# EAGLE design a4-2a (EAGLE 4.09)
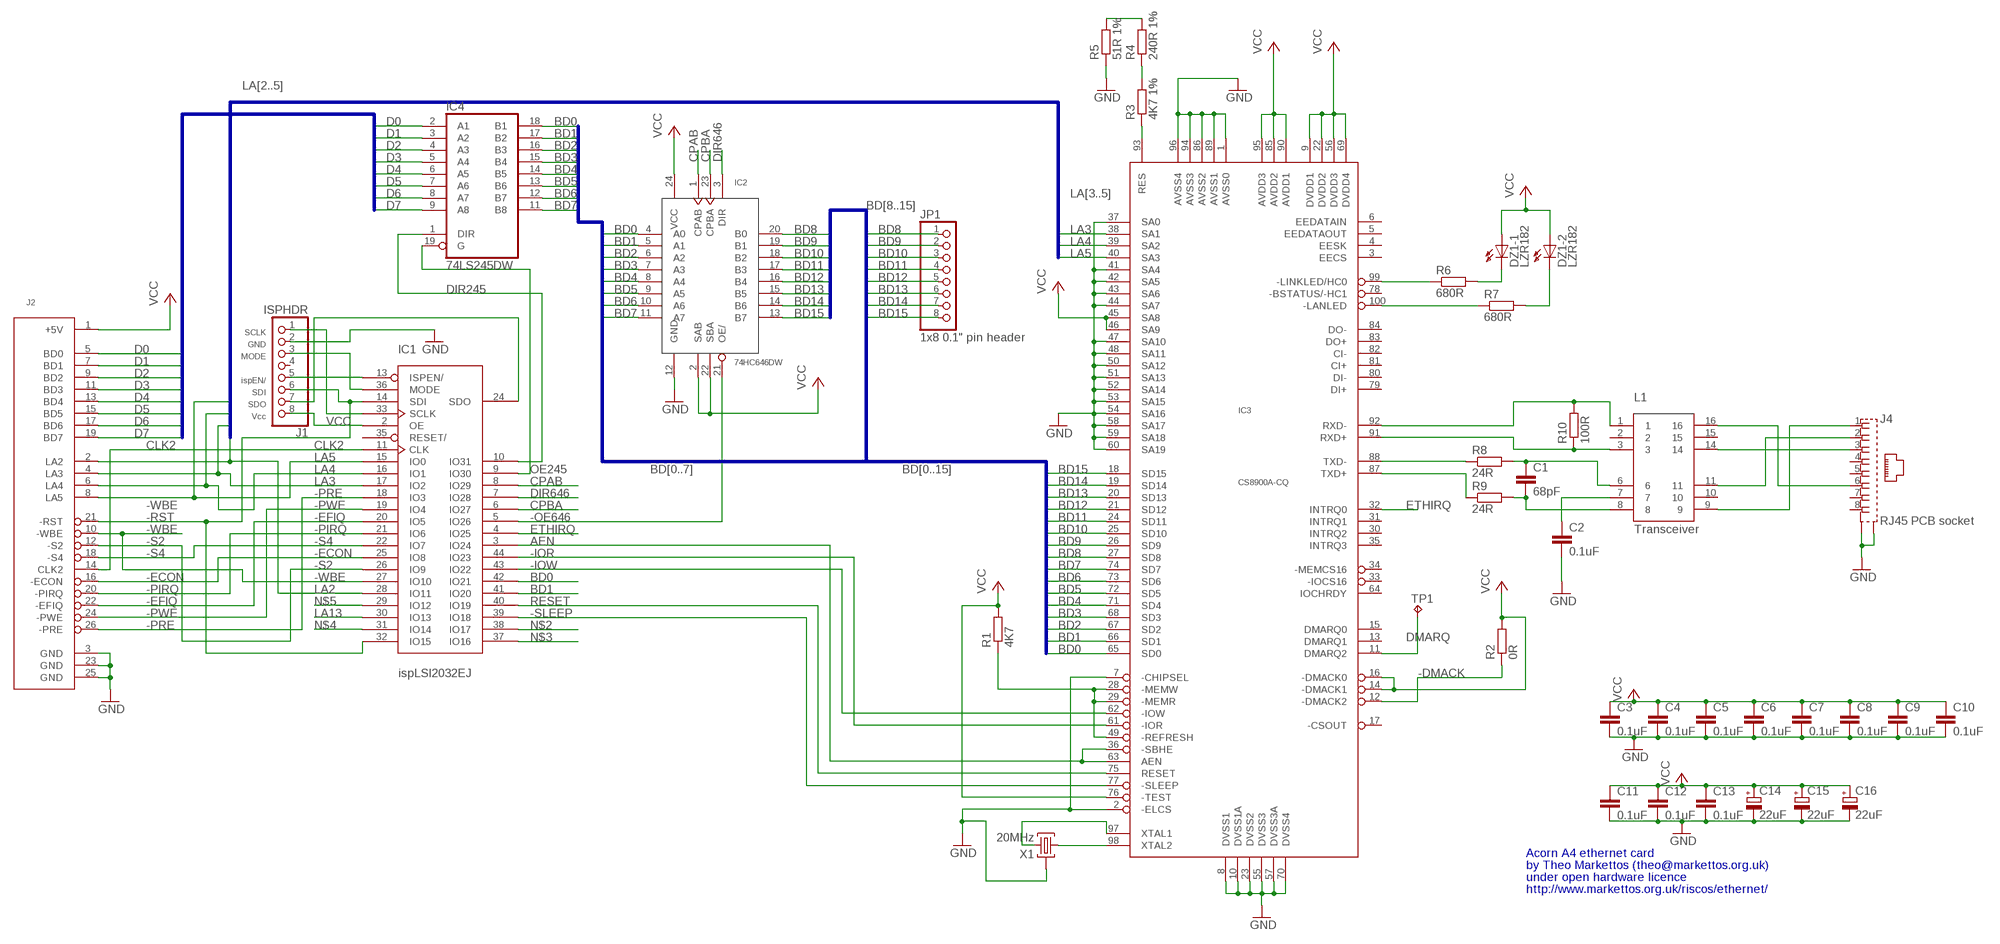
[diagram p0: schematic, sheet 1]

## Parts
C1  68pF  C-EU025-030X050  [C025-030X050]
C2  0.1uF  C-EUC0805  [C0805]
C3  0.1uF  C-EUC0805  [C0805]
C4  0.1uF  C-EUC0805  [C0805]
C5  0.1uF  C-EUC0805  [C0805]
C6  0.1uF  C-EUC0805  [C0805]
C7  0.1uF  C-EUC0805  [C0805]
C8  0.1uF  C-EUC0805  [C0805]
C9  0.1uF  C-EUC0805  [C0805]
C10  0.1uF  C-EUC0805  [C0805]
C11  0.1uF  C-EUC0805  [C0805]
C12  0.1uF  C-EUC0805  [C0805]
C13  0.1uF  C-EUC0805  [C0805]
C14  22uF  CPOL-EUE2-5  [E2-5]
C15  22uF  CPOL-EUE2-5  [E2-5]
C16  22uF  CPOL-EUE2-5  [E2-5]
DZ1  LZR182  [LZR182]
IC1  ispLSI2032EJ  ISP2032  [PLCC-44]
IC2  74HC646DW  74646DW  [SO24W]
IC3  CS8900A-CQ  CS8900  [TQFP100]
IC4  74LS245DW  [SO20W]
J1  ISPHDR  [1X08]
J2  2x13 2mm header r/a  A4ECONET  [26WDIL2MM]
J4  RJ45 PCB socket  556591-1  [556591-1]
JP1  1x8 0.1" pin header  PINHD-1X8  [1X08]
L1  Transceiver  10BASET-TXRX  [DIL16/12]
R1  4K7  R-EU_M0805  [M0805]
R2  0R  R-EU_M0805  [M0805]
R3  4K7 1%  R-EU_R0603  [R0603]
R4  240R 1%  R-EU_R0603  [R0603]
R5  51R 1%  R-EU_R0603  [R0603]
R6  680R  R-EU_R0603  [R0603]
R7  680R  R-EU_R0603  [R0603]
R8  24R  R-EU_R0603  [R0603]
R9  24R  R-EU_R0603  [R0603]
R10  100R  R-EU_R0603  [R0603]
TP1  TP08SQ  [TP08SQ]
X1  20MHz  HC49TL-H  [HC49TL-H]

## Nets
-DMACK: IC3.12(-DMACK2) R2.1
-ECON: IC1.25(IO8) J2.16(-ECON)
-EFIQ: IC1.20(IO5) J2.22(-EFIQ)
-IOR: IC1.44(IO23) IC3.61(-IOR)
-IOW: IC1.43(IO22) IC3.62(-IOW)
-ISPEN: IC1.13(ISPEN/) J1.5(ISPEN/)
-LANLED: IC3.100(-LANLED) R7.1
-LINKLED: IC3.99(-LINKLED/HC0) R6.1
-OE646: IC1.5(IO26) IC2.21(OE/)
-PIRQ: IC1.21(IO6) J2.20(-PIRQ)
-PRE: IC1.18(IO3) J2.26(-PRE)
-PWE: IC1.19(IO4) J2.24(-PWE)
-RST: IC1.14(SDI) IC1.32(IO15) J1.6(SDI) J2.21(-RST)
-S2: IC1.26(IO9) J2.12(-S2)
-S4: IC1.22(IO7) J2.18(-S4)
-SLEEP: IC1.39(IO18) IC3.77(-SLEEP)
-WBE: IC1.27(IO10) J2.10(-WBE)
AEN: IC1.3(IO24) IC3.36(-SBHE) IC3.63(AEN)
BD0: IC1.42(IO21) IC2.4(A0) IC3.65(SD0) IC4.18(B1)
BD1: IC1.41(IO20) IC2.5(A1) IC3.66(SD1) IC4.17(B2)
BD2: IC2.6(A2) IC3.67(SD2) IC4.16(B3)
BD3: IC2.7(A3) IC3.68(SD3) IC4.15(B4)
BD4: IC2.8(A4) IC3.71(SD4) IC4.14(B5)
BD5: IC2.9(A5) IC3.72(SD5) IC4.13(B6)
BD6: IC2.10(A6) IC3.73(SD6) IC4.12(B7)
BD7: IC2.11(A7) IC3.74(SD7) IC4.11(B8)
BD8: IC2.20(B0) IC3.27(SD8) JP1.1
BD9: IC2.19(B1) IC3.26(SD9) JP1.2
BD10: IC2.18(B2) IC3.25(SD10) JP1.3
BD11: IC2.17(B3) IC3.24(SD11) JP1.4
BD12: IC2.16(B4) IC3.21(SD12) JP1.5
BD13: IC2.15(B5) IC3.20(SD13) JP1.6
BD14: IC2.14(B6) IC3.19(SD14) JP1.7
BD15: IC2.13(B7) IC3.18(SD15) JP1.8
CLK2: IC1.11(CLK) J2.14(CLK2)
CPAB: IC1.8(IO29) IC2.1(CPAB)
CPBA: IC1.6(IO27) IC2.23(CPBA)
D0: IC4.2(A1) J2.5(BD0)
D1: IC4.3(A2) J2.7(BD1)
D2: IC4.4(A3) J2.9(BD2)
D3: IC4.5(A4) J2.11(BD3)
D4: IC4.6(A5) J2.13(BD4)
D5: IC4.7(A6) J2.15(BD5)
D6: IC4.8(A7) J2.17(BD6)
D7: IC4.9(A8) J2.19(BD7)
DIR245: IC1.10(IO31) IC4.1(DIR)
DIR646: IC1.7(IO28) IC2.3(DIR)
DMARQ: IC3.11(DMARQ2) TP1.TP
ETHIRQ: IC1.4(IO25) IC3.32(INTRQ0)
GND [power]: C2.2 C3.2 C4.2 C5.2 C6.2 C7.2 C8.2 C9.2 C10.2 C11.2 C12.2 C13.2 C14.- C15.- C16.- IC2.12(GND) IC3.1(AVSS0) IC3.2(-ELCS) IC3.7(-CHIPSEL) IC3.8(DVSS1) IC3.10(DVSS1A) IC3.23(DVSS2) IC3.37(SA0) IC3.41(SA4) IC3.42(SA5) IC3.43(SA6) IC3.44(SA7) IC3.47(SA10) IC3.48(SA11) IC3.50(SA12) IC3.51(SA13) IC3.52(SA14) IC3.53(SA15) IC3.54(SA16) IC3.55(DVSS3) IC3.57(DVSS3A) IC3.58(SA17) IC3.59(SA18) IC3.60(SA19) IC3.70(DVSS4) IC3.86(AVSS2) IC3.89(AVSS1) IC3.94(AVSS3) IC3.96(AVSS4) J1.2(GND) J2.3(GND) J2.23(GND) J2.25(GND) J4.G1(S1) J4.G2(S2) R5.1 X1.3
LA2: IC1.28(IO11) J2.2(LA2)
LA3: IC1.17(IO2) IC3.38(SA1) J2.4(LA3)
LA4: IC1.16(IO1) IC3.39(SA2) J2.6(LA4)
LA5: IC1.15(IO0) IC3.40(SA3) J2.8(LA5)
LA13: IC1.30(IO13)
MODE: IC1.36(MODE) J1.3(MODE)
N$2: IC1.38(IO17)
N$3: IC1.37(IO16)
N$4: IC1.31(IO14)
N$5: IC1.29(IO12)
N$6: R4.2 R5.2
N$7: R3.2 R4.1
N$8: IC3.93(RES) R3.1
N$9: IC3.97(XTAL1) X1.2
N$11: DZ1.K1(-1:C) R6.2
N$12: DZ1.K2(-2:C) R7.2
N$17: C2.1 L1.7
N$18 [tx]: C1.1 L1.6 R8.2
N$21 [tx]: C1.2 L1.8 R9.2
N$22: J4.6 L1.16
N$23: J4.3 L1.14
N$24: J4.2 L1.11
N$25: J4.1 L1.9
N$33: IC1.33(SCLK) J1.1(SCLK)
OE245: IC1.9(IO30) IC4.19(G)
PULLUP: IC3.28(-MEMW) IC3.29(-MEMR) IC3.49(-REFRESH) R1.1
RESET: IC1.40(IO19) IC3.75(RESET)
RXD+ [rx]: IC3.91(RXD+) L1.3 R10.1
RXD- [rx]: IC3.92(RXD-) L1.1 R10.2
SDO: IC1.24(SDO) J1.7(SDO)
TXD+ [tx]: IC3.87(TXD+) R9.1
TXD- [tx]: IC3.88(TXD-) R8.1
VCC [power]: C3.1 C4.1 C5.1 C6.1 C7.1 C8.1 C9.1 C10.1 C11.1 C12.1 C13.1 C14.+ C15.+ C16.+ DZ1.A1(-1:A) DZ1.A2(-2:A) IC1.2(OE) IC2.2(SAB) IC2.22(SBA) IC2.24(VCC) IC3.9(DVDD1) IC3.14(-DMACK1) IC3.16(-DMACK0) IC3.22(DVDD2) IC3.45(SA8) IC3.46(SA9) IC3.56(DVDD3) IC3.69(DVDD4) IC3.76(-TEST) IC3.85(AVDD2) IC3.90(AVDD1) IC3.95(AVDD3) J1.8(VCC) J2.1(+5V) R1.2 R2.2
XTAL2: IC3.98(XTAL2) X1.1
Unconnected: IC1.35(RESET/) IC3.3(EECS) IC3.4(EESK) IC3.5(EEDATAOUT) IC3.6(EEDATAIN) IC3.13(DMARQ1) IC3.15(DMARQ0) IC3.17(-CSOUT) IC3.30(INTRQ2) IC3.31(INTRQ1) IC3.33(-IOCS16) IC3.34(-MEMCS16) IC3.35(INTRQ3) IC3.64(IOCHRDY) IC3.78(-BSTATUS/-HC1) IC3.79(DI+) IC3.80(DI-) IC3.81(CI+) IC3.82(CI-) IC3.83(DO+) IC3.84(DO-) J1.4(N/C) J4.4 J4.5 J4.7 J4.8 L1.2 L1.10 L1.15

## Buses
BD[0..7]
LA[2..5]
BD[8..15]
BD[0..15]
LA[3..5]

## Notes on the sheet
- Acorn A4 ethernet card
- by Theo Markettos (theo@markettos.org.uk)
- under open hardware licence
- http://www.markettos.org.uk/riscos/ethernet/

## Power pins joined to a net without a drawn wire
GND: IC1.1(GND) IC1.23(GND) IC4.10(GND)
VCC: IC1.12(VCC) IC1.34(VCC) IC4.20(VCC)

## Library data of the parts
C1-C13 = rcl:C-EU: CAPACITOR, European symbol
C14-C16 = rcl:CPOL-EU: POLARIZED CAPACITOR, European symbol
DZ1 = led:LZR182: LED BLOCK 2 LEDs, Siemens
IC1 = lattice:ISP2032
IC2 = misc:74*646: 74xx646DW Octal transceiver/register with 3-state outputs (SOIC24)
IC3 = cirrus89x0:CS8900: Cirrus Logic CS8900 ethernet controller (100-pin TQFP package)
IC4 = 74xx-us:74*245: Octal BUS TRANSCEIVER, 3-state
J1 = lattice:ISPHDR: 8-pin header for in-circuit programming cable
J2 = acorn:A4ECONET: Acorn A4 computer Econet bay interface
J4 = con-amp:556591-1: AMP connector
JP1 = pinhead:PINHD-1X8: PIN HEADER
L1 = misc:10BASET-TXRX
R1-R10 = rcl:R-EU_: RESISTOR, European symbol
TP1 = testpad:TP08SQ: TEST PIN
X1 = crystal:HC49TL-H: CRYSTAL

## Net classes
1 power: width 0.635 mm, drill 0.254 mm
2 rx: width 0.635 mm
3 tx: width 2.54 mm

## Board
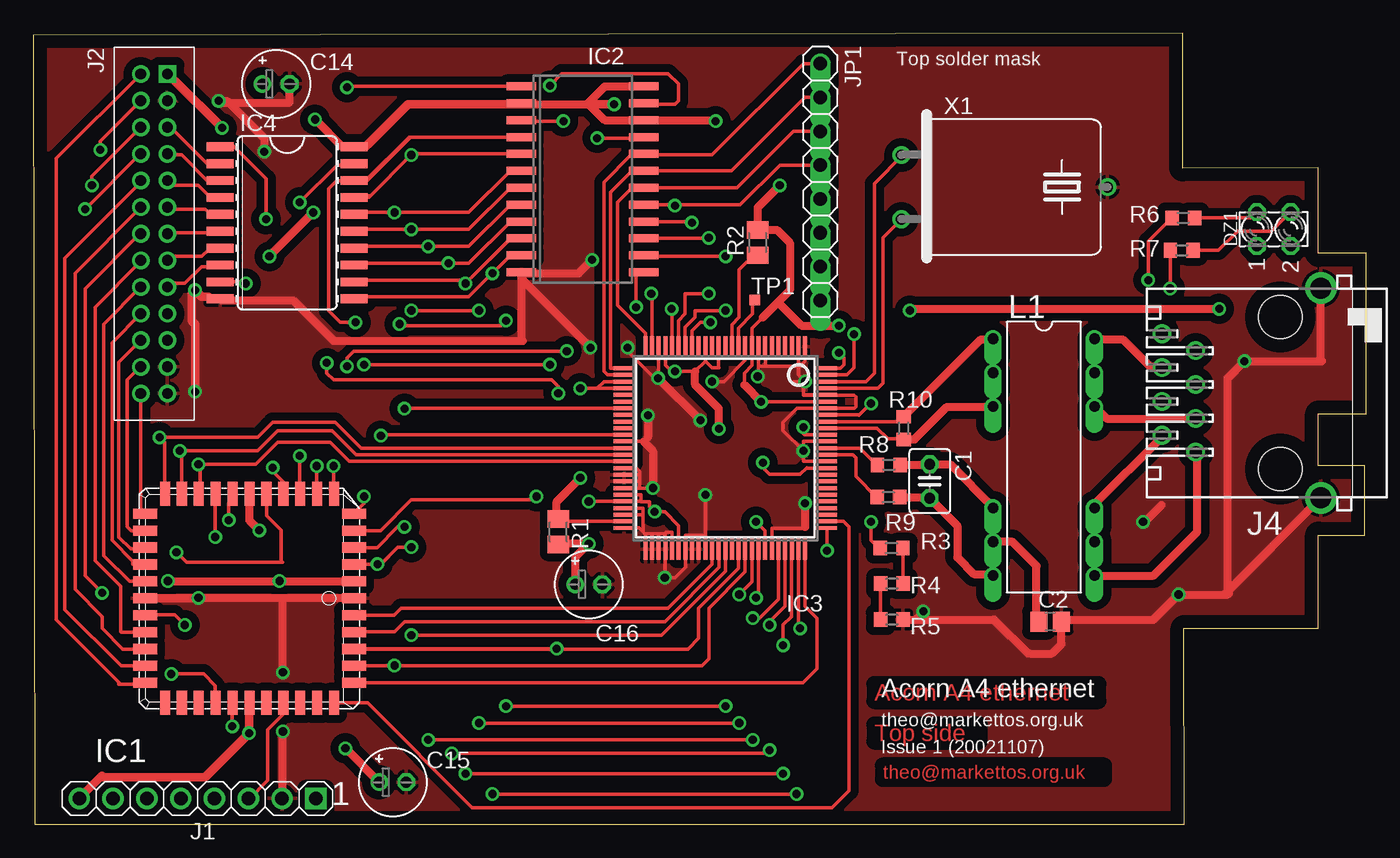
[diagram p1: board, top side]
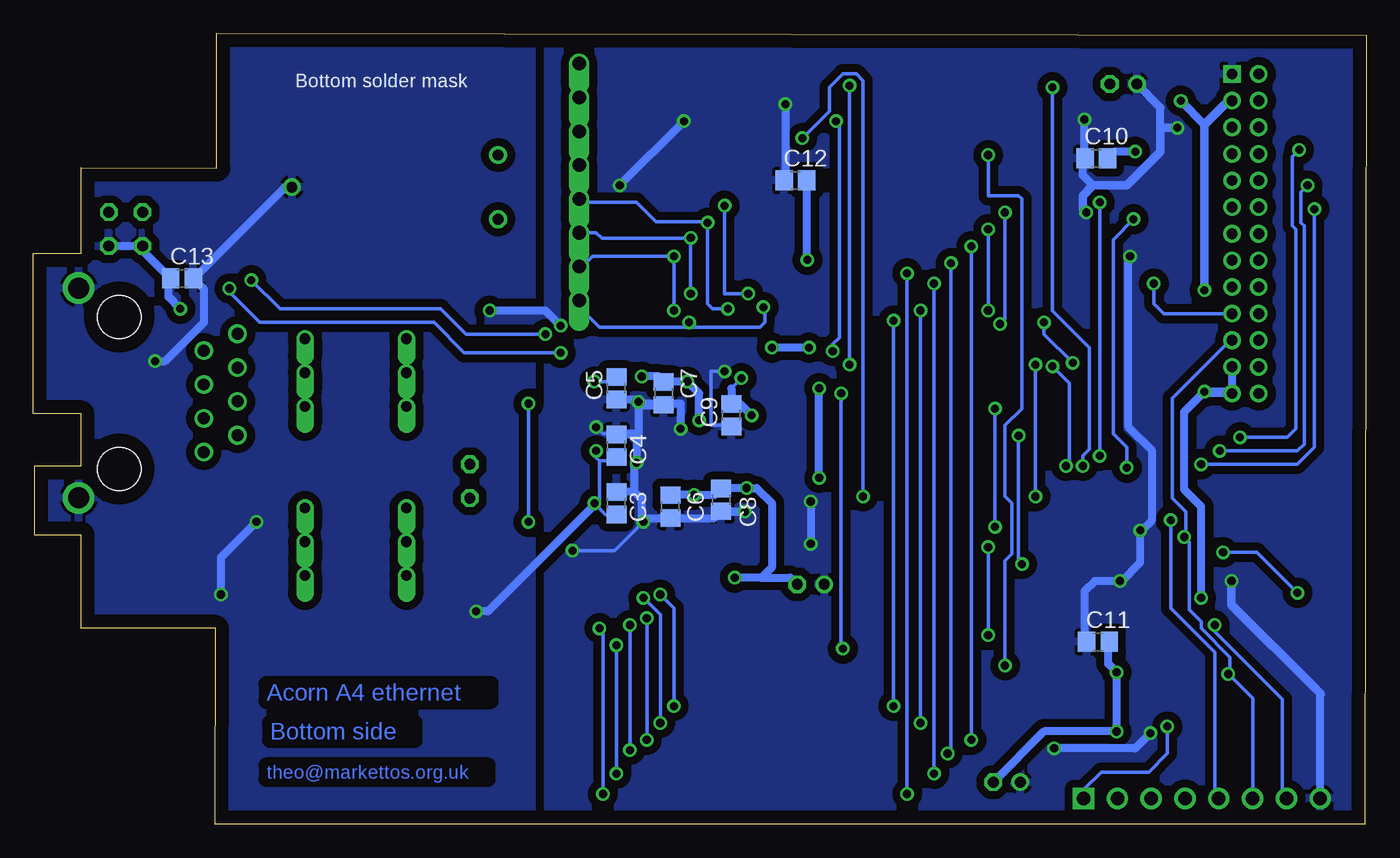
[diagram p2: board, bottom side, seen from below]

Size 100.17 x 59.43 mm. Coordinates in mm from the lower left corner, seen from the top.
Outline: 0.1,0 86.5,0 86.47,14.73 96.57,14.73 96.57,21.73 100.07,21.73 100.07,26.93 96.57,26.93 96.57,30.83 100.17,30.83 100.17,42.9 96.57,42.9 96.57,49.33 86.37,49.3 86.37,59.43 0,59.3 0.1,0
Copper layers used: Top, Bottom

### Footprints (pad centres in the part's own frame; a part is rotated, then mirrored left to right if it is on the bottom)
C025-030X050 = drill 0.813 octagon: 1 -1.27,0; 2 1.27,0
C0805 = smd 1.3 x 1.5: 1 -0.85,0; 2 0.85,0
E2-5 = drill 0.813 pad 1.27 round: + -1.016,0 | drill 0.813 pad 1.27 octagon: - 1.016,0
LZR182 = drill 0.813 octagon: A1 -1.27,1.27; A2 -1.27,-1.27; K1 1.27,1.27; K2 1.27,-1.27
PLCC-44 = smd 1.803 x 0.762: 1 -7.849,0; 2 -7.849,-1.27; 3 -7.849,-2.54; 4 -7.849,-3.81; 5 -7.849,-5.08; 6 -7.849,-6.35; 18 7.849,-6.35; 19 7.849,-5.08; 20 7.849,-3.81; 21 7.849,-2.54; 22 7.849,-1.27; 23 7.849,0; 24 7.849,1.27; 25 7.849,2.54; 26 7.849,3.81; 27 7.849,5.08; 28 7.849,6.35; 40 -7.849,6.35; 41 -7.849,5.08; 42 -7.849,3.81; 43 -7.849,2.54; 44 -7.849,1.27 | smd 0.762 x 1.803: 7 -6.35,-7.849; 8 -5.08,-7.849; 9 -3.81,-7.849; 10 -2.54,-7.849; 11 -1.27,-7.849; 12 0,-7.849; 13 1.27,-7.849; 14 2.54,-7.849; 15 3.81,-7.849; 16 5.08,-7.849; 17 6.35,-7.849; 29 6.35,7.849; 30 5.08,7.849; 31 3.81,7.849; 32 2.54,7.849; 33 1.27,7.849; 34 0,7.849; 35 -1.27,7.849; 36 -2.54,7.849; 37 -3.81,7.849; 38 -5.08,7.849; 39 -6.35,7.849
SO24W = smd 0.6 x 2.2: 1 -6.985,-4.6; 2 -5.715,-4.6; 3 -4.445,-4.6; 4 -3.175,-4.6; 5 -1.905,-4.6; 6 -0.635,-4.6; 7 0.635,-4.6; 8 1.905,-4.6; 9 3.175,-4.6; 10 4.445,-4.6; 11 5.715,-4.6; 12 6.985,-4.6; 13 6.985,4.6; 14 5.715,4.6; 15 4.445,4.6; 16 3.175,4.6; 17 1.905,4.6; 18 0.635,4.6; 19 -0.635,4.6; 20 -1.905,4.6; 21 -3.175,4.6; 22 -4.445,4.6; 23 -5.715,4.6; 24 -6.985,4.6
TQFP100 = smd 0.3 x 1.6: 1 -6.2,-7.6; 2 -5.7,-7.6; 3 -5.2,-7.6; 4 -4.7,-7.6; 5 -4.2,-7.6; 6 -3.7,-7.6; 7 -3.2,-7.6; 8 -2.7,-7.6; 9 -2.2,-7.6; 10 -1.7,-7.6; 11 -1.2,-7.6; 12 -0.7,-7.6; 13 -0.2,-7.6; 14 0.3,-7.6; 15 0.8,-7.6; 16 1.3,-7.6; 17 1.8,-7.6; 18 2.3,-7.6; 19 2.8,-7.6; 20 3.3,-7.6; 21 3.8,-7.6; 22 4.3,-7.6; 23 4.8,-7.6; 24 5.3,-7.6; 25 5.8,-7.6; 51 5.8,7.6; 52 5.3,7.6; 53 4.8,7.6; 54 4.3,7.6; 55 3.8,7.6; 56 3.3,7.6; 57 2.8,7.6; 58 2.3,7.6; 59 1.8,7.6; 60 1.3,7.6; 61 0.8,7.6; 62 0.3,7.6; 63 -0.2,7.6; 64 -0.7,7.6; 65 -1.2,7.6; 66 -1.7,7.6; 67 -2.2,7.6; 68 -2.7,7.6; 69 -3.2,7.6; 70 -3.7,7.6; 71 -4.2,7.6; 72 -4.7,7.6; 73 -5.2,7.6; 74 -5.7,7.6; 75 -6.2,7.6 | smd 1.6 x 0.3: 26 7.4,-6; 27 7.4,-5.5; 28 7.4,-5; 29 7.4,-4.5; 30 7.4,-4; 31 7.4,-3.5; 32 7.4,-3; 33 7.4,-2.5; 34 7.4,-2; 35 7.4,-1.5; 36 7.4,-1; 37 7.4,-0.5; 38 7.4,0; 39 7.4,0.5; 40 7.4,1; 41 7.4,1.5; 42 7.4,2; 43 7.4,2.5; 44 7.4,3; 45 7.4,3.5; 46 7.4,4; 47 7.4,4.5; 48 7.4,5; 49 7.4,5.5; 50 7.4,6; 76 -7.8,6; 77 -7.8,5.5; 78 -7.8,5; 79 -7.8,4.5; 80 -7.8,4; 81 -7.8,3.5; 82 -7.8,3; 83 -7.8,2.5; 84 -7.8,2; 85 -7.8,1.5; 86 -7.8,1; 87 -7.8,0.5; 88 -7.8,0; 89 -7.8,-0.5; 90 -7.8,-1; 91 -7.8,-1.5; 92 -7.8,-2; 93 -7.8,-2.5; 94 -7.8,-3; 95 -7.8,-3.5; 96 -7.8,-4; 97 -7.8,-4.5; 98 -7.8,-5; 99 -7.8,-5.5; 100 -7.8,-6
SO20W = smd 0.66 x 2.032: 1 -5.715,-5.029; 2 -4.445,-5.029; 3 -3.175,-5.029; 4 -1.905,-5.029; 5 -0.635,-5.029; 6 0.635,-5.029; 7 1.905,-5.029; 8 3.175,-5.029; 9 4.445,-5.029; 10 5.715,-5.029; 11 5.715,5.029; 12 4.445,5.029; 13 3.175,5.029; 14 1.905,5.029; 15 0.635,5.029; 16 -0.635,5.029; 17 -1.905,5.029; 18 -3.175,5.029; 19 -4.445,5.029; 20 -5.715,5.029
1X08 = drill 1.016 pad 1.6 square: 1 -8.89,0 | drill 1.016 pad 1.6 round: 2 -6.35,0; 3 -3.81,0; 4 -1.27,0; 5 1.27,0; 6 3.81,0; 7 6.35,0; 8 8.89,0
26WDIL2MM = drill 0.813 square: 1 -16,6 | drill 0.813 round: 2 -16,4; 3 -14,6; 4 -14,4; 5 -12,6; 6 -12,4; 7 -10,6; 8 -10,4; 9 -8,6; 10 -8,4; 11 -6,6; 12 -6,4; 13 -4,6; 14 -4,4; 15 -2,6; 16 -2,4; 17 0,6; 18 0,4; 19 2,6; 20 2,4; 21 4,6; 22 4,4; 23 6,6; 24 6,4; 25 8,6; 26 8,4
556591-1 = drill 0.889 round: 1 -4.445,6.35; 2 -3.175,8.89; 3 -1.905,6.35; 4 -0.635,8.89; 5 0.635,6.35; 6 1.905,8.89; 7 3.175,6.35; 8 4.445,8.89 | drill 1.575 pad 2.184 round: G1 -7.874,-3.048; G2 7.874,-3.048 | hole 3.251: -5.715,0; 5.715,0
1X08' = drill 1.016 offset: 1 -8.89,0; 2 -6.35,0; 3 -3.81,0; 4 -1.27,0; 5 1.27,0; 6 3.81,0; 7 6.35,0; 8 8.89,0
DIL16/12 = drill 0.813 offset: 1 -8.89,-3.81; 2 -6.35,-3.81; 3 -3.81,-3.81; 6 3.81,-3.81; 7 6.35,-3.81; 8 8.89,-3.81; 9 8.89,3.81; 10 6.35,3.81; 11 3.81,3.81; 14 -3.81,3.81; 15 -6.35,3.81; 16 -8.89,3.81
M0805 = smd 1.3 x 1.6: 1 -0.95,0; 2 0.95,0
R0603 = smd 1 x 1.1: 1 -0.85,0; 2 0.85,0
TP08SQ = smd 0.8 x 0.8: TP 0,0
HC49TL-H = drill 0.813 round: 1 -2.413,-7.62; 2 2.413,-7.62; 3 0,7.874

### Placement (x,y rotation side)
C1  67.37,25.78 270 top
C2  76.42,15.24 0 top
C3  56.35,24.13 270 bottom
C4  56.35,28.44 270 bottom
C5  56.35,32.76 90 bottom
C6  52.29,23.87 90 bottom
C7  52.79,32.38 90 bottom
C8  48.48,24.38 90 bottom
C9  47.71,30.73 90 bottom
C10  20.28,50.03 0 bottom
C11  20.15,13.71 0 bottom
C12  42.89,48.38 0 bottom
C13  88.99,41.02 0 bottom
C14  18.25,55.62 0 top
C15  27.01,3.17 0 top
C16  41.74,18.03 0 top
DZ1  93.22,44.72 90 top
IC1  16.25,16.99 180 top
IC2  41.28,48.46 270 top
IC3  51.8,28.27 180 top
IC4  19.08,45.19 270 top
J1  12.35,1.95 180 top
J2  4.08,40.37 270 top
J4  93.71,32.41 90 top
JP1  1x8 0.1" pin header  [1X08']  59.14,48.26 270 top
L1  75.94,27.58 270 top
R1  39.45,21.98 270 top
R2  54.43,43.71 90 top
R3  64.5,20.76 0 top
R4  64.53,18.09 180 top
R5  64.52,15.38 180 top
R6  86.42,45.57 0 top
R7  86.3,43.13 0 top
R8  64.29,27 0 top
R9  64.26,24.59 0 top
R10  65.4,29.77 90 top
TP1  54.22,39.4 0 top
X1  72.86,47.87 270 top

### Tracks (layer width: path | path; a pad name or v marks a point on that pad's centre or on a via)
-DMACK
  Top 0.254: IC3.12 52.5,37.55 53.05,38.1 53.05,41.65 54.32,42.92 54.43,42.81 R2.1
-ECON
  Top 0.254: IC1.25 6.59,14.45 6.57,14.47 6.57,17.9 4.66,19.81 4.66,38.86 8.09,42.29 8.08,42.3 J2.16
-EFIQ
  Top 0.254: J2.22 6.44,34.73 6.44,21.59 7.33,20.7 8.47,20.7 8.4,20.77 IC1.20
-IOR
  Top 0.254: IC3.61 51,20.58 51.02,20.57 51.02,19.55 47.71,16.25 27.65,16.25 27.11,15.72 IC1.44
-IOW
  Top 0.254: IC1.43 24.13,14.47 27.14,14.47 27.9,15.24 47.46,15.24 51.52,19.3 51.52,20.82 51.5,20.8 IC3.62
-ISPEN  (via drill 0.61)
  Top 0.254: v14.69,22.86 14.69,24.13 IC1.13
  Bottom 0.254: v14.69,22.86 14.69,16.25 11.39,12.95 11.39,2.28 11.06,1.95 | 11.06,1.95 11.01,1.9 | J1.5 11.06,1.95
-LANLED  (via drill 0.61)
  Top 0.254: 85.43,43.14 85.43,43.18 | 85.43,43.14 R7.1 | v85.43,40.26 85.43,43.14 | IC3.100 60.65,34.27 60.92,34.54 60.92,35.05 v60.54,35.43 60.92,35.43
  Bottom 0.254: v85.43,40.26 85.56,40.13 83.15,37.71 70.07,37.71 67.78,35.43 60.92,35.43 v60.54,35.43
-LINKLED  (via drill 0.61)
  Top 0.254: IC3.99 61.16,33.77 61.68,34.29 v61.68,36.83 | R6.1 85.56,45.59 83.78,43.81 v83.78,40.89
  Bottom 0.254: v61.68,36.83 67.65,36.83 69.56,38.73 81.62,38.73 v83.78,40.89
-OE646  (via drill 0.61)
  Top 0.254: IC1.5 26.1,22.07 28.41,24.38 37.55,24.38 v37.81,24.63 | IC2.21 46.11,51.63 46.19,51.56 v42.38,51.56
  Bottom 0.254: v37.81,24.63 37.81,55.88 38.32,56.38 39.33,56.38 40.35,55.37 40.35,53.59 v42.38,51.56
-PIRQ
  Top 0.254: IC1.21 7.48,19.53 7.48,19.78 5.93,21.33 5.93,36.19 8.09,38.35 J2.20
-PRE
  Top 0.254: J2.26 8.09,32.38 | J2.26 | J2.26 8.09,23.74 8.47,23.36 8.43,23.36 8.56,23.24 | 8.56,23.24 8.5,23.24 IC1.18 | 8.56,23.24 8.73,23.24
-PWE
  Top 0.254: 8.08,34.4 8.09,34.41 | 8.08,34.4 J2.24 | 8.08,34.4 7.07,33.4 7.07,22.35 7.36,22.07 IC1.19 8.4,22.03 8.47,21.97 8.47,22
-RST  (via drill 0.61)
  Top 0.254: IC1.14 13.68,24.8 v13.68,21.59 | v10.38,11.3 12.79,11.3 13.68,10.41 13.68,9.27 13.81,9.14 13.8,9.14 IC1.32
  Bottom 0.254: J2.21 10.2,36.37 14.57,32 14.57,24.51 13.55,23.49 13.55,21.59 | 13.55,21.59 13.68,21.46 | 13.55,21.59 v13.68,21.59 13.3,21.2 13.3,16.12 12.41,15.24 12.41,14.73 10.25,12.57 10.25,11.43 v10.38,11.3 8.54,9.46 J1.6
-S2
  Top 0.254: IC1.26 6.72,13.18 5.17,14.73 5.17,15.62 3.14,17.65 3.14,41.4 8.09,46.35 J2.12
-S4
  Top 0.254: IC1.22 7.23,18.26 5.3,20.19 5.3,37.59 J2.18 | J2.18 8.09,40.38 | J2.18
-SLEEP
  Top 0.254: IC1.39 25.11,9.14 32.98,1.27 60.03,1.27 61.3,2.54 61.3,22.35 60.88,22.77 IC3.77
-WBE
  Top 0.254: IC1.27 6.59,11.91 2.38,16.12 2.38,42.54 8.2,48.37 | 8.2,48.37 8.22,48.38 | J2.10 8.09,48.38 8.19,48.38 8.2,48.37
AEN  (via drill 0.61)
  Top 0.254: IC1.3 26.1,19.53 27.39,20.82 | 27.39,20.82 v28.41,20.82 | v25.87,19.55 26.12,19.55 27.39,20.82 | v28.41,14.22 47.21,14.22 52,19.02 IC3.63 | 26.13,29.22 v26.12,29.21 26.18,29.27 IC3.36
  Bottom 0.254: v26.12,29.21 26.12,19.81 v25.87,19.55 | v28.41,20.82 v28.41,14.22
BD0  (via drill 0.61)
  Top 0.254: 24.12,13.18 49.21,13.18 50,13.97 50,16.25 53,19.25 IC3.65 | IC1.42 24.12,13.18 | 24.12,13.18 26.1,13.18 26.12,13.2 | 24.12,13.18 24.09,13.2 | IC2.4 28.23,51.63 24.98,48.38 24.12,48.38 IC4.18 | IC4.18 25.09,48.37 28.28,51.56 | IC4.18 22.81,48.37 22.19,47.75 22.19,38.6 23.08,37.71 v24.22,37.71 | v22.06,34.67 22.06,33.91 22.57,33.4 38.95,33.4 39.46,32.89 v39.46,32.38 | 24.12,13.18 24.15,13.2 v39.33,13.2
  Bottom 0.254: v24.22,37.71 24.22,36.83 v22.06,34.67 | v39.33,13.2 39.46,13.2 v39.46,32.38
BD1  (via drill 0.61)
  Top 0.254: IC1.41 24.13,11.93 | IC2.5 28.49,50.37 v28.41,50.29 | v28.41,50.29 25.36,47.24 24.09,47.24 24.11,47.22 IC4.17 25.22,47.1 v28.41,50.29 | 24.13,11.93 24.09,11.93 | 24.13,11.93 v27.14,11.93 50.25,11.93 50.76,12.44 50.76,16.25 53.5,18.99 IC3.66
  Bottom 0.254: v28.41,50.29 28.41,47.24 26.12,47.24 25.87,46.99 25.87,31.24 27.14,29.97 27.14,24.63 26.63,24.13 26.63,20.32 27.14,19.81 v27.14,11.93
BD2  (via drill 0.61)
  Top 0.254: 32.73,45.97 25.11,45.97 IC4.16 | 32.73,45.97 35.78,49.02 IC2.6 35.85,49.1 32.73,45.97 | v27.14,45.97 32.73,45.97 | v35.52,8.89 v52.03,8.89 | v27.52,37.59 27.52,37.46 35.14,37.46 v35.52,37.84 | IC3.67 54,18.22 v53.05,17.27
  Bottom 0.254: v52.03,8.89 52.03,16.25 v53.05,17.27 | v27.14,45.97 27.14,37.97 v27.52,37.59 27.27,37.33 | v35.52,8.89 v35.52,37.84
BD3  (via drill 0.61)
  Top 0.254: 32.73,44.7 25.11,44.7 IC4.15 | 32.73,44.7 35.78,47.75 IC2.7 35.85,47.82 32.73,44.7 | v28.41,44.7 32.73,44.7 | v33.49,38.6 v28.41,38.6 | v33.49,7.62 v53.05,7.62 | IC3.68 54.5,17.2 v54.32,17.01
  Bottom 0.254: v28.41,38.6 v28.41,44.7 | v33.49,7.62 v33.49,38.6 | v53.05,7.62 53.05,15.74 v54.32,17.01
BD4  (via drill 0.61)
  Top 0.254: 32.73,43.43 25.11,43.43 IC4.14 | 32.73,43.43 35.78,46.48 IC2.8 35.85,46.55 32.73,43.43 | v29.68,43.43 32.73,43.43 | v54.06,15.49 54.57,15.49 56,16.92 IC3.71 | v29.68,6.35 v54.06,6.35
  Bottom 0.254: v29.68,6.35 v29.68,43.43 | 53.81,6.35 54.06,6.09 v54.06,6.35 v54.06,15.49
BD5  (via drill 0.61)
  Top 0.254: 32.73,42.16 25.11,42.16 IC4.13 | 32.73,42.16 35.78,45.21 IC2.9 35.85,45.29 32.73,42.16 | v31.2,42.16 32.73,42.16 | v31.46,5.33 55.08,5.33 v55.33,5.58 | v55.33,14.98 55.33,15.24 56.48,16.38 56.48,20.64 IC3.72
  Bottom 0.254: v31.2,42.16 31.2,5.58 v31.46,5.33 | v55.33,5.58 v55.33,14.98
BD6  (via drill 0.61)
  Top 0.254: IC4.12 25.11,40.89 32.73,40.89 35.78,43.94 IC2.10 35.85,44.01 v32.47,40.64 | v56.35,13.46 56.35,14.98 56.98,15.62 56.98,20.65 IC3.73 57.02,20.67 | v32.47,3.81 v56.35,3.81
  Bottom 0.254: v32.47,3.81 v32.47,40.64 | v56.35,3.81 v56.35,13.46
BD7  (via drill 0.61)
  Top 0.254: 35.78,42.67 32.73,39.62 25.11,39.62 IC4.11 | 35.78,42.67 IC2.11 36.11,42.74 | IC3.74 57.5,14.85 v57.62,14.73 | v34.51,2.28 v57.37,2.28 | 35.78,42.67 35.9,42.67 | 35.78,42.67 | v34.51,41.4 35.78,42.67 | 35.78,42.67
  Bottom 0.254: v57.37,2.28 57.37,14.47 v57.62,14.73 | v34.51,2.28 v34.51,41.4
BD8
  Top 0.254: 43.14,33.78 42.89,34.03 42.89,48.26 44.92,50.29 IC2.20 45.76,50.37 45.68,50.29 51.02,50.29 57.87,57.15 JP1.1 59.4,57.15 | 43.14,33.78 | IC3.27 43.15,33.77 43.14,33.78
BD9
  Top 0.254: 43.4,40.38 43.4,47.49 44.92,49.02 IC2.19 52.46,49.1 57.97,54.61 JP1.2 | 43.4,40.38 | IC3.26 43.4,34.27 43.4,40.38
BD10
  Top 0.254: JP1.3 57.11,52.07 52.87,47.82 IC2.18 44.92,47.75 43.9,46.73 43.9,38.98 46,36.89 IC3.25
BD11  (via drill 0.61)
  Top 0.254: 48.14,46.55 IC2.17 | v48.22,46.48 48.14,46.55 | 48.14,46.55 53.12,46.55 56.1,49.53 JP1.4 | IC3.24 46.5,39.82 v46.44,39.87
  Bottom 0.254: v48.22,46.48 48.22,39.87 v46.44,39.87
BD12  (via drill 0.61)
  Top 0.254: 49.49,45.29 IC2.16 | 49.49,45.29 49.49,45.34 | v49.49,45.21 49.49,45.29 | IC3.21 48,38.7 v47.97,38.73
  Bottom 0.254: 49.49,45.29 53.38,45.29 54.83,46.73 58.89,46.73 JP1.5 | v47.97,38.73 49.11,38.73 49.49,39.11 v49.49,45.21 49.49,45.29 | 49.49,45.29 49.49,45.34
BD13  (via drill 0.61)
  Top 0.254: 50.76,44.01 IC2.15 | v50.76,39.87 48.98,39.87 48.98,38.35 48.48,37.84 48.48,35.89 IC3.20 | 50.76,44.01 50.76,43.94 | v50.76,44.07 50.76,44.01
  Bottom 0.254: v50.76,39.87 50.76,43.94 50.76,44.01 | 50.76,44.01 57.44,44.01 57.87,44.45 JP1.6 | 50.76,44.01 v50.76,44.07
BD14  (via drill 0.61)
  Top 0.254: IC2.14 45.95,42.67 v52.03,42.67 | v52.03,38.6 49.75,38.6 49.75,38.1 48.98,37.33 48.98,35.88 IC3.19
  Bottom 0.254: v52.03,38.6 v52.03,42.67 58.13,42.67 58.89,41.91 JP1.7
BD15  (via drill 0.61)
  Top 0.254: IC3.18 49.5,36.31 49.49,36.32 49.49,37.08 50.13,37.71 v50.89,37.71 | IC2.13 45.88,41.34 45.17,41.34 45.17,41.52 45.3,41.4 v45.3,38.86
  Bottom 0.254: JP1.8 59.14,38.86 57.62,37.33 50.89,37.33 | 50.89,37.33 45.55,37.33 45.17,37.71 45.17,38.73 v45.3,38.86 | 50.89,37.33 v50.89,37.71
CLK2  (via drill 0.61)
  Top 0.254: IC1.11 17.52,23.2 18.63,22.09 18.63,19.81 18.76,19.68 11.52,19.68 v10.76,20.44 | v5.17,17.4 3.9,18.66 3.9,40.26 8.08,44.44 | 8.08,44.44 8.09,44.45 | 8.08,44.44 J2.14
  Bottom 0.254: v10.76,20.44 8.22,20.44 v5.17,17.4
CPAB  (via drill 0.61)
  Top 0.254: 23.58,55.45 IC2.1 | IC1.8 21.3,24.87 v21.3,26.92
  Top 0.406: v23.58,55.37 23.58,55.45
  Bottom 0.254: v23.58,55.37 23.58,38.6 20.79,35.81 20.79,28.19 21.3,27.68 v21.3,26.92 21.3,26.79
CPBA  (via drill 0.61)
  Top 0.254: 45.95,54.1 IC2.23 45.94,54.12 45.94,54.1 48.22,54.1 48.48,54.35 48.48,55.62 47.71,56.38 39.71,56.38 v38.82,55.49 | v24.85,34.54 v38.82,34.54 | IC1.6 24.1,23.35 24.09,23.36 24.85,24.13 v24.85,24.63
  Bottom 0.254: v24.85,24.63 v24.85,34.54 | v38.82,34.54 v38.82,55.49
D0
  Top 0.254: IC4.2 14.06,49.65 | IC4.2 | IC4.2 13.93,49.53 13.17,49.53 10.63,52.07 10.38,52.07 J2.5
D1
  Top 0.254: IC4.3 13.06,48.37 11.14,50.29 10,50.29 | 10,50.29 | J2.7 10,50.29
D2
  Top 0.254: IC4.4 14.06,47.11 13.93,47.24 13.17,47.24 12.41,48 10.38,48 10.12,48.26 10.12,48.38 10.09,48.38 J2.9
D3
  Top 0.254: 14.05,45.72 14.06,45.72 | 14.05,45.72 IC4.5 | 14.05,45.72 13.81,45.97 13.17,45.97 12.92,46.22 10.25,46.22 10.08,46.39 | 10.08,46.39 10,46.48 | J2.11 10.08,46.39
D4
  Top 0.254: 14.17,44.56 14.19,44.57 | 14.17,44.56 IC4.6 | 14.17,44.56 14.06,44.45 10.25,44.45 10.12,44.32 J2.13
D5
  Top 0.254: IC4.7 14.06,43.3 | IC4.7 | IC4.7 13.93,43.18 13.17,43.18 12.66,42.67 10.5,42.67 10.12,42.29 10.08,42.33 J2.15
D6
  Top 0.254: 14.19,41.91 14.07,42.02 IC4.8 | 14.19,41.91 12.66,41.91 11.39,40.64 10.25,40.64 10,40.38 10.01,40.37 J2.17 | 14.19,41.91
D7  (via drill 0.61)
  Top 0.254: 14.95,40.64 IC4.9 15.85,40.75 v15.96,40.64
  Bottom 0.254: v15.96,40.64 15.96,39.11 15.2,38.35 10,38.35 10.02,38.37 J2.19
DIR245  (via drill 0.61)
  Top 0.254: 14.95,51.05 | IC4.1 14.81,50.91 14.95,51.05 | 14.95,51.05 17.49,48.51 v17.49,45.46 | 18.79,24.85 18.76,24.89 | IC1.10 18.79,24.85 | v18,26.79 18,26.54 18.79,25.74 18.79,24.85
  Bottom 0.254: 19.01,42.03 19.01,42.16 | v17.49,45.46 19.01,43.94 19.01,42.03 | 19.01,42.03 19.01,29.33 18,28.32 v18,26.79
DIR646  (via drill 0.61)
  Top 0.254: IC1.7 22.31,25.12 22.33,25.12 22.57,24.89 v22.57,26.92 | IC2.3 36.75,52.83 v39.84,52.83 | v23.58,34.41 23.58,35.05 24.09,35.56 v40.09,35.56
  Bottom 0.254: v22.57,26.92 22.31,27.17 22.31,33.14 v23.58,34.41 | v39.84,52.83 39.59,52.57 39.59,36.57 40.09,36.06 v40.09,35.56
DMARQ
  Top 0.254: TP1.TP 54.1,39.4 54.06,39.37 54.06,38.35 53,37.29 IC3.11
ETHIRQ  (via drill 0.61)
  Top 0.254: IC1.4 25.84,20.8 27.39,22.35 v27.9,22.35 | IC3.32 27.93,31.27 v27.9,31.24
  Bottom 0.254: v27.9,22.35 v27.9,31.24
GND  (via drill 0.61)
  Top 0.254: IC3.7 55.02,35.87 55.02,34.47 55.08,34.41 | IC3.2 57.49,35.86 57.49,34.41 | v58,33.27 58,33.14 | IC3.44 45.55,25.27 | v46.57,25.27 45.55,25.27 | 47.46,21.84 46.95,21.84 | 46.95,21.84 46.44,21.84 | 46.44,21.84 45.94,21.84 | 47.46,20.71 IC3.54 | 47.46,20.71 47.46,21.84 | 54.5,34.48 IC3.8 | 54.5,34.48 54.57,34.41 55.08,34.41 | 54.5,34.48 54.5,33.71 v54.45,33.65 | v50.51,24.76 v50.5,24.76 IC3.60 50.5,21.71 | 50,21.71 IC3.59 50,21.71 | 50,21.71 | IC3.37 45.87,28.77 45.88,28.77 46.19,29.08 | IC3.41 45.33,26.77 45.55,26.54 45.55,26.28 | 45.55,25.78 45.55,26.28 | 45.55,25.27 45.55,25.78 | IC3.43 45.54,25.77 45.55,25.78 | IC3.42 45.54,26.27 45.55,26.28 | 55.08,34.41 57.49,34.41 | 57.49,34.41 57.62,34.41 58,34.8 IC3.1 | 57.49,34.41 57.49,33.78 v58,33.27 | v58,33.27 57.87,33.27 | 57.87,33.27 57.11,33.27 | v44.67,35.81 44.67,35.56 46.7,33.52 v46.95,33.52 47,33.57 IC3.23 | IC3.55 48,21.93 47.55,21.93 47.46,21.84 | IC3.70 55.5,22.26 57.91,22.26 58,22.35 | 66.28,15.38 R5.1 | IC3.10 53.5,34.87 51.91,33.27 v51.02,33.27 | 58,33.14 57.87,33.27 | 58,33.14 58,32.89 | 57.87,33.27 57.87,32.25 | 47.46,20.71 v47.46,18.54 48.22,18.54 49,19.32 IC3.57 49,21.71 49.49,21.71 | 74.77,12.82 74.89,12.82 75.02,12.7 | IC3.89 57.87,28.77 v57.87,28.06 | IC3.86 57.87,27.27 v57.87,28.06 | v57.87,28.06 56.35,29.59 56.35,30.22 57.39,31.27 IC3.94 61.71,31.27 61.81,31.37 61.81,32.13 61.68,32.25 57.87,32.25 | 89.37,17.14 89.49,17.26 89.49,17.27 | 89.75,17.52 89.88,17.65 | IC3.52 46.5,21.78 46.44,21.84 | IC3.53 47,21.79 46.95,21.84 | IC3.96 57.89,32.27 57.87,32.25 | IC3.51 46,21.77 45.94,21.84 | IC3.50 45.51,22.27 45.81,21.97 | 45.94,21.84 45.81,21.97 | IC3.48 45.81,23.27 45.81,23.24
  Top 0.254: 45.81,21.97 45.81,23.24 | IC3.47 45.81,23.77 45.81,23.24 | 49.49,21.71 50,21.71 | IC3.58 49.5,21.71 49.49,21.71 | 50,21.71 50.5,21.71 | 50.5,21.71 50.51,21.71
  Top 0.61: v18.76,11.43 18.76,17.01 | IC1.1 24.32,16.99 24.35,17.01 18.76,17.01 | 18.76,17.01 18.73,16.99 IC1.23 12.38,16.99 v12.41,17.01 | 36.68,41 IC2.12 36.66,41.46 36.66,41.4 40.98,41.4 v42,42.41 | 36.68,41 v41.87,35.81 | 36.68,41 36.68,36.43 36.79,36.32 22.57,36.32 19.52,39.37 14.19,39.37 14.07,39.48 IC4.10 13.31,39.48 13.17,39.62 | 45.87,28.77 46.57,28.06 v46.57,25.27 | v46.19,30.73 46.19,29.08 | v58,24.13 58,22.35 | v13.93,54.35 14.06,54.35 | 14.06,54.35 14.57,54.35 17.36,51.56 v17.36,50.54 | C14.- 19.27,54.23 14.19,54.23 14.06,54.35 | v66.89,16 66.28,15.38 | R5.1 72.2,15.38 74.77,12.82 | 74.89,12.82 76.54,12.82 77.27,13.55 C2.2 77.14,15.36 | J4.G2 96.76,40.36 96.74,40.38 96.74,34.92 96.86,34.79 v91.02,34.79 89.75,33.52 89.75,17.52 89.75,17.27 | v46.95,33.52 v50.13,30.35 | 77.14,15.36 77.05,15.36 | 77.14,15.36 82.89,15.36 | 82.89,15.36 83.02,15.36 | 82.89,15.36 84.16,15.36 v86.07,17.27 89.75,17.27 | 96.73,24.51 J4.G1 89.49,17.27 89.75,17.27 | J1.2 18.7,1.97 18.76,2.03 v18.76,6.98 | v83.4,22.73 83.53,22.73 84.8,24 | 89.75,17.27 89.88,17.4 | 13.17,39.62 | 89.88,17.65 89.88,17.78
  Top 0.635: 13.17,39.62 12.66,39.62 v12.15,40.13 11.9,39.87 11.9,37.84 12.15,37.59 v12.15,32.51
  Bottom 0.254: v46.95,33.52 47.71,32.76 | 56.35,27.68 C4.2 56.35,27.3 57.62,27.3 | 56.73,33.65 56.77,33.61 C5.2 56.35,33.65 56.73,33.65 | v58,33.27 57.11,33.27 56.73,33.65 | 56.22,23.11 56.35,23.24 C3.2 57.15,23.28 v58,24.13 58,24 57.62,24 57.62,27.3 | 48.44,25.27 C8.2 | 52.29,24.76 C6.2 | 53.17,33.65 52.79,33.27 C7.2 | J2.23 10.12,34.41 | C9.2 47.04,31.58 | v57.87,28.06 57.87,27.55 57.62,27.3
  Bottom 0.61: v18.76,11.43 18.7,11.37 | v41.87,35.81 v44.67,35.81 | 47.71,32.76 C9.2 | 48.44,25.27 v46.57,25.27 45.81,25.27 44.67,24.13 44.67,19.3 45.43,18.54 45.55,18.54 | 48.95,24.76 v50.51,24.76 52.29,24.76 | 53.17,33.65 v54.45,33.65 | J2.23 J2.25 12.02,32.37 v12.15,32.51 13.68,30.98 13.68,25.14 12.41,23.87 v12.41,17.01 12.41,16.89 | 45.55,18.54 v47.46,18.54 | 47.04,31.58 v46.19,30.73 | 12.15,52.57 | 12.15,52.57 v13.93,54.35 | C10.2 19.39,50.03 18.88,50.54 v17.36,50.54 | C11.2 19.39,13.62 19.39,12.06 v18.76,11.43 | C12.2 42.04,42.45 v42,42.41 | C16.- 43.27,18.54 45.55,18.54 | v66.89,16 66,16 58,24 | v50.13,30.35 50.13,32.38 v51.02,33.27 52.79,33.27 | v91.02,34.79 90.89,34.67 90.89,34.79 90.26,34.79 87.34,37.71 87.34,40.22 C13.2 88.23,41.02 88.35,40.89 88.23,40.89 81.24,47.87 X1.3 | v18.76,11.43 v18.76,6.98 24.22,6.98 C15.- | v86.07,17.27 86.07,20.06 v83.4,22.73 | J2.3 10.1,54.35 10.38,54.35 10.63,54.1
  Bottom 0.635: 10.63,54.1 12.15,52.57 v12.15,40.13 | v12.15,32.51 10.63,32.51 J2.25
  pour Top (isolate 0.61): -1.44,60.57 -1.44,-1.66 102.07,-1.66 102.07,60.57
  pour Bottom (isolate 0.61): 62.7,59.94 100.16,59.94 100.16,-1.66 62.7,-1.66
LA2
  Top 0.254: J2.2 1.74,50.03 1.74,15.36 6.47,10.64 6.44,10.61 6.44,10.54 8.3,10.54 IC1.28
LA3  (via drill 0.61)
  Top 0.254: IC3.38 24.65,28.27 22.7,30.22 18,30.22 16.85,29.08 v9.49,29.08 9.87,28.7 9.87,24.87 IC1.17 | J2.4 5.04,51.33 v5.04,50.67
  Bottom 0.254: v9.49,29.08 5.93,29.08 5.3,29.71 5.3,44.7 5.55,44.95 5.55,50.16 v5.04,50.67
LA4  (via drill 0.61)
  Top 0.254: IC3.39 24.26,27.77 22.44,29.59 18.38,29.59 16.85,28.06 v11.01,28.06 11.14,27.94 11.14,25.02 | IC1.16 11.21,24.84 11.27,24.89 11.14,25.02 | 11.14,25.02 11.14,24.89 | J2.6 4.41,48.7 v4.41,48
  Bottom 0.254: v11.01,28.06 5.17,28.06 4.66,28.57 4.66,44.95 4.92,45.21 4.92,47.49 v4.41,48
LA5  (via drill 0.61)
  Top 0.254: IC3.40 23.75,27.27 22.31,28.7 18.38,28.7 16.73,27.05 v12.41,27.05 12.54,26.92 12.54,24.89 12.43,24.89 12.41,24.87 IC1.15 | 8.08,50.4 8.09,50.41 | 8.08,50.4 J2.8 | v3.9,46.22 8.08,50.4
  Bottom 0.254: v12.41,27.05 5.17,27.05 3.9,28.32 v3.9,46.22
MODE
  Top 0.254: IC1.36 18.79,8.29 17.61,7.11 17.61,3.3 16.22,1.9 16.17,1.95 J1.3
N$6
  Top 0.254: 63.7,15.38 63.72,15.36 | R5.2 63.7,15.38 | R4.2 63.68,15.4 63.7,15.38
N$7
  Top 0.254: 65.3,18.09 65.24,18.03 | R4.1 65.3,18.09 | R3.2 65.35,18.14 65.3,18.09
N$8  (via drill 0.61)
  Top 0.254: IC3.93 62.03,30.77 62.06,30.73 v62.95,31.62 | R3.1 63.59,20.7 62.95,21.33 v62.95,22.73
  Bottom 0.254: v62.95,22.73 v62.95,31.62
N$9
  Top 0.254: IC3.97 63.47,32.77 63.84,33.14 63.84,44.07 X1.2
N$11
  Top 0.254: DZ1.K1 91.93,45.99 91.51,45.57 R6.2
N$12
  Top 0.254: R7.2 89.07,43.13 90.51,44.57 93.05,44.57 94.47,45.99 DZ1.K2
N$17
  Top 0.61: L1.7 73.59,21.23 75.4,19.43 75.4,15.62 75.65,15.36 75.57,15.27 C2.1
N$18
  Top 0.254: C1.1 67.39,27.05 67.4,27.05 67.36,27
  Top 0.61: R8.2 67.36,27 | L1.6 72.13,23.84 68.92,27.05 C1.1
N$21
  Top 0.254: 67.39,24.51 C1.2
  Top 0.61: 67.53,24.38 67.39,24.51 67.32,24.59 R9.2 | C1.2 69.43,22.45 69.43,20.06 70.7,18.79 72.1,18.79 72.1,18.73 L1.8
N$22
  Top 0.61: L1.16 79.78,36.45 81.88,36.45 83.91,34.41 84.8,34.41 84.8,34.34 J4.6
N$23
  Top 0.61: 87.39,30.48 87.47,30.48 | 87.39,30.48 J4.3 | L1.14 80.67,30.48 87.39,30.48
N$24
  Top 0.61: J4.2 84.82,29.1 79.75,24.03 L1.11
N$25
  Top 0.61: L1.9 84.19,18.69 87.47,21.97 87.47,27.81 87.36,27.91 J4.1
N$33  (via drill 0.61)
  Top 0.254: v14.95,7.36 14.95,8.38 IC1.33
  Bottom 0.254: v14.95,7.36 14.95,5.33 16.34,3.93 19.9,3.93 21.17,2.66 21.17,2.02 J1.1
OE245  (via drill 0.61)
  Top 0.254: v20.03,27.68 20.03,25.65 IC1.9 | v20.03,46.73 22.82,49.53 23.33,49.53 IC4.19
  Bottom 0.254: v20.03,27.68 v20.03,46.73
PULLUP  (via drill 0.61)
  Top 0.254: IC3.49 39.55,22.77 39.33,22.98 39.38,22.93 R1.1 | v41.11,32.77 v41.11,32.76 42.38,32.76 | IC3.28 42.88,33.27 42.38,32.76 | IC3.29 42.38,32.77 42.38,32.76
  Top 0.61: v41.11,26.03 39.33,24.25 39.33,22.98
  Bottom 0.61: v41.11,26.03 v41.11,32.76
RESET
  Top 0.254: IC1.40 57.85,10.64 58.89,11.68 58.89,15.49 58,16.38 IC3.75
RXD+
  Top 0.254: IC3.91 63.41,29.77 64.22,28.95 65.37,28.95 | 65.37,28.95 R10.1 | 65.37,28.95 65.49,28.95 | L1.3 72.1,31.37
  Top 0.61: R10.1 66.23,28.92 68.67,31.37 72.1,31.37
RXD-
  Top 0.254: R10.2 65.39,30.62 65.03,30.27 IC3.92
  Top 0.61: L1.1 72.11,36.45 71.22,36.45 R10.2
SDO  (via drill 0.61)
  Top 0.254: v11.39,14.98 10.63,15.74 9.11,15.74 IC1.24
  Bottom 0.254: v11.39,14.98 11.39,14.47 6.31,9.39 6.31,2.28 5.98,1.95 | 5.98,1.95 5.93,1.9 | J1.7 5.98,1.95
TXD+
  Top 0.254: IC3.87 61.6,27.77 61.81,27.55 61.81,26.16 63.38,24.59 R9.1
TXD-
  Top 0.254: 63.44,26.94 63.46,26.92 | 63.44,26.94 R8.1 | IC3.88 62.12,28.27 63.44,26.94
VCC  (via drill 0.61)
  Top 0.254: IC3.16 50.5,34.8 50.51,34.79 | 51.52,35.84 IC3.14 51.5,34.31 51.52,34.29 51.02,34.29 50.51,34.79 | IC3.95 54.72,31.77 v54.7,31.75 | v54.83,27.17 54.83,26.79 55.33,26.28 57.62,26.28 58.13,26.79 58.16,26.77 IC3.85 | IC3.45 45.68,24.76 45.68,24.25 | v48.22,34.03 49.49,34.03 | v48.22,34.03 49.75,34.03 50.51,34.79 | v41.74,24.25 41.76,24.27 IC3.46 45.67,24.27 45.68,24.25 | 39.46,21.08 39.45,21.07 R1.2 | 45.68,24.25 46.32,24.25 46.32,23.87 v46.7,23.49 47.46,23.49 48.5,22.45 IC3.56 | 54.83,38.1 54,37.27 IC3.9 54,34.48 53.43,33.91 53.43,33.02 | v57.87,29.84 57.87,29.33 57.94,29.27 IC3.90 | IC3.76 59.65,22.22 v59.65,20.57 | 47.53,35.87 IC3.22 47.5,34.5 47.97,34.03 v48.22,34.03 | IC3.69 55,22.05 v54.32,22.73
  Top 0.61: 24.35,18.28 | IC1.12 16.25,22.82 v16.98,22.09 | v21.04,45.97 | v17.74,42.67 v21.04,45.97 | v56.1,48 54.43,46.34 R2.2 55.88,44.66 56.86,43.68 56.86,40.13 55.97,39.24 | 55.97,39.24 54.83,38.1 | 53.43,33.02 v54.7,31.75 | 39.46,21.08 v41.74,21.08 40.73,20.06 C16.+ | 49.75,34.03 49.75,33.02 51.52,31.24 v51.52,29.71 | v23.46,5.71 C15.+ | v10.12,18.28 | 24.35,18.28 | v10.12,18.28 v18.5,18.28 | v18.5,18.28 24.35,18.28 | IC1.2 24.07,18.28 v18.5,18.28 | v43.65,54.1 43.78,54.1 | v60.54,37.46 57.75,37.46 55.97,39.24 | v65.88,38.6 66,38.73 v89.12,38.73 | 24.12,50.92 24.22,50.92 | 24.12,50.92 IC4.20 24.1,50.92 24.09,50.92 | v21.17,52.96 23.2,50.92 24.09,50.92 | 24.09,50.92 24.12,50.92 | 25.11,51.05 24.98,50.92 24.09,50.92 | IC2.24 42.96,55.45 41.62,54.1 41.74,54.1 | 41.74,54.1 42.94,52.9 IC2.22 51.19,52.9 v51.27,52.83 | v43.65,54.1 35.78,54.1 35.65,54.1 | v43.65,54.1 | 35.65,54.1 | IC2.2 35.73,54.18 35.65,54.1 | v43.65,54.1 41.74,54.1 | 5.3,3.55 | 5.3,3.55 5.07,3.55 5.07,3.58 | 5.07,3.58 5.17,3.68 | J1.8 3.46,1.97 5.07,3.58
  Top 0.635: v14.19,52.32 10.63,55.88 J2.1 | 35.78,54.1 28.16,54.1 25.11,51.05 | 5.3,3.55 12.92,3.55 v16.22,6.85 16.22,8.38 IC1.34
  Bottom 0.254: C9.1 47.8,29.97 49.24,29.97 49.24,34.03 v48.22,34.03 | C4.1 56.35,29.21 | 54.83,31.75 56.22,31.75 | 54.91,29.29 54.83,29.21 | 52.29,22.98 C6.1 | v54.32,22.73 54.06,22.98 | 54.45,22.98 54.32,22.86 | 52.79,31.49 C7.1 | v54.83,27.17 55.04,26.96 | 56.22,31.75 56.35,31.75 | 56.22,31.75 56.35,31.62 | v57.87,29.84 57.37,29.33 56.35,29.33 | 54.32,22.86 54.32,22.98 | v59.65,20.57 56.48,20.57 v54.32,22.73 | 54.32,22.86 54.32,23.24 | 54.32,22.86 v54.32,22.73
  Bottom 0.61: v51.27,52.83 v56.1,48 | 54.91,29.29 C4.1 56.35,29.33 54.7,29.33 v54.7,31.75 | 54.83,29.21 v54.83,27.17 | 54.06,22.98 52.29,22.98 49.02,22.98 48.52,23.49 v46.7,23.49 48.44,23.49 C8.1 | 55.04,24.98 C3.1 | 55.04,24.98 54.45,24.38 54.45,22.98 | 55.04,26.96 55.04,24.98 | v41.74,24.25 v41.74,21.08 | v16.22,6.85 17.36,5.71 v23.46,5.71 | C12.1 43.65,48.47 v43.65,54.1 | v65.88,38.6 61.68,38.6 v60.54,37.46 | v89.12,38.73 90,39.62 90,40.89 89.88,41.02 | C11.1 21.17,13.71 21.17,17.52 20.41,18.28 v18.5,18.28 18.38,18.28 16.98,19.68 v16.98,22.09 16.85,22.09 16.09,22.86 16.09,28.06 17.87,29.84 17.87,42.67 v17.74,42.67 | 89.88,41.02 C13.1 | 89.88,41.02 91.91,43.05 91.91,43.43 | 91.91,43.43 91.93,43.43 DZ1.A1 | DZ1.A2 94.47,43.43 91.91,43.43 | 52.79,31.49 54.45,31.49 v54.7,31.75 | v54.7,31.75 54.83,31.75 | C5.1 54.7,31.91 v54.7,31.75 | v54.7,31.75 54.57,31.62 51.52,31.62 v51.52,29.71 | 15.46,52.32 15.46,53.84 C14.+ | 21.17,50.03 21.3,50.03 21.3,48.76 20.54,48 | 21.17,50.03 C10.1 | 21.17,50.03 v21.17,52.96 | 3.77,10.16 3.39,9.77 | J1.8 3.46,9.84 3.77,10.16 | 3.77,10.16
  Bottom 0.635: v14.19,52.32 15.46,52.32 15.46,50.54 18,48 20.54,48 21.3,47.24 21.3,46.22 v21.04,45.97 | v10.12,18.28 10.12,16.51 3.77,10.16
  pour Bottom (isolate 0.61, rank 2): -1.44,60.57 -1.44,-1.66 102.07,-1.66 102.07,60.57
XTAL2
  Top 0.254: IC3.98 62.57,33.27 63.21,33.91 63.21,48.13 65.37,50.29 X1.1

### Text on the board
Top: Acorn A4 ethernet | Top side | theo@markettos.org.uk
Bottom: Acorn A4 ethernet | Bottom side | theo@markettos.org.uk
tNames: Top solder mask | Acorn A4 ethernet | theo@markettos.org.uk | Issue 1 (20021107)
bNames: Bottom solder mask
_layer121: 1 | 2 | 1
_layer125: JP1 | J2 | C14 | IC2 | Top solder mask | X1 | IC4 | R6 | R2 | R7 | DZ1 | TP1 | L1 | R10 | R8 | C1 | J4 | R1 | R9 | R3 | R4 | IC3 | R5 | C2 | C16 | Acorn A4 ethernet | IC1 | theo@markettos.org.uk | Issue 1 (20021107) | C15 | J1
_layer126: Bottom solder mask | C10 | C12 | C13 | C7 | C5 | C9 | C4 | C3 | C6 | C8 | C11
_layer127: 74HC646DW | 20MHz | 74LS245DW | 0R | TP08SQ | Transceiver | 68pF | CS8900A | 4K7 | ispLSI2032EJ | 22uF | 0.1uF | 22uF
_layer128: 0.1uF | 0.1uF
